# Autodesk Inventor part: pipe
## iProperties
Shininess: 64.0
Length Units: 11269
Angle Units: 11279
Time Units: 11290
Mass Units: 11283
Length Display Precision: 3
Angle Display Precision: 2
Compacted: True
Part Number: pipe
Document SubType Name: Modeling
Created: 2004-07
Designer: Peter
Manufacturer: Standard
Standards Organization: Custom
Density: 0.0
Volumn: 0.0
Area: 0.0
PropertySet Name: Model Information
Control State: 0
Master: False
Checked Out: False
Author: Peter
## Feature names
1. Revolution3
